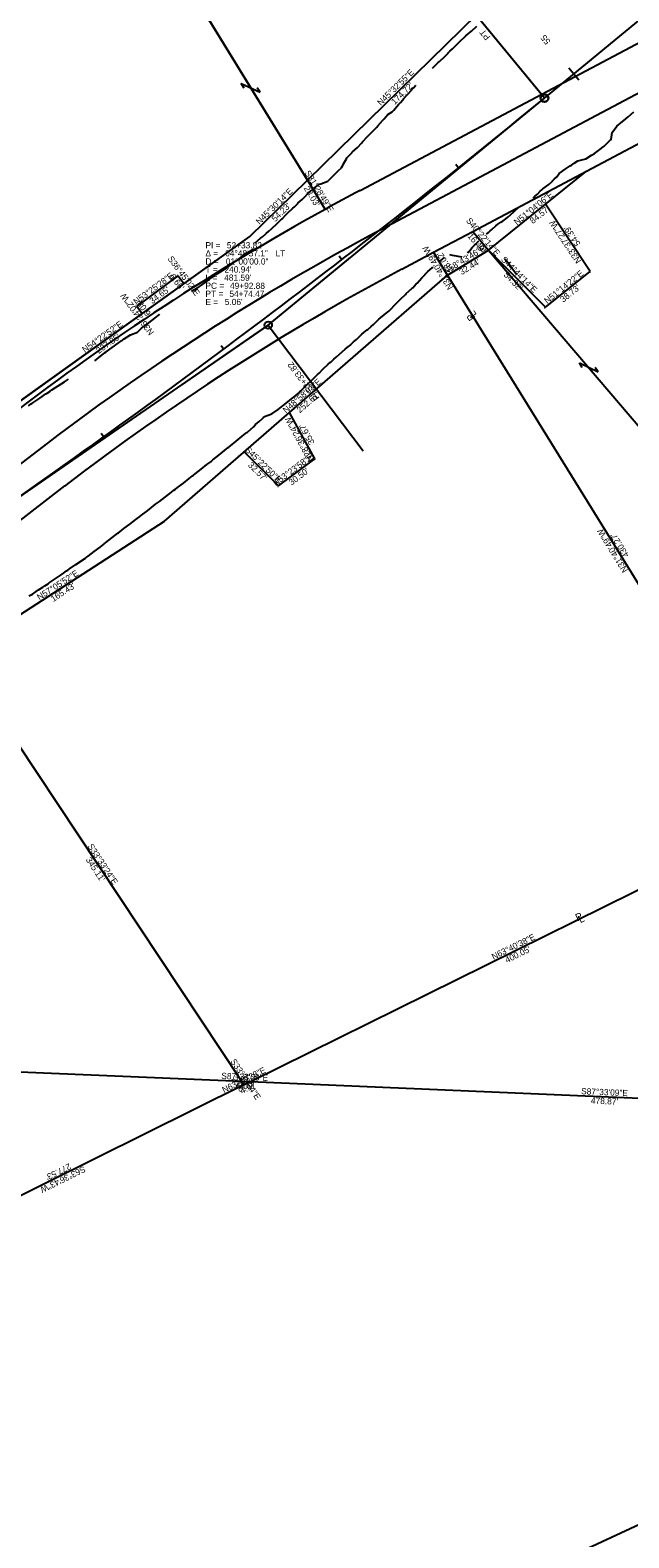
# Model space of a CAD drawing. Extents: x 1145508 to 2262867, y -3126236 to 2021677.
# Drawn here: x 1148331 to 1148734, y 2017346 to 2018362 of the extents above; entities that cross this region are included whole.
import ezdxf

# ---------------------------------------------------------------- set-up
doc = ezdxf.new("R2010")
doc.units = 0
for name, color, linetype in [('Default', 7, 'Continuous'), ('DSN_RDWY_Alignment', 7, 'Continuous'), ('DSN_RDWY_Alignment Annotation', 7, 'Continuous'), ('DSN_RDWY_Const Limits', 7, 'Continuous'), ('DSN_ROW_Annotation', 7, 'Continuous'), ('DSN_ROW_Esmnt', 7, 'Continuous'), ('DSN_ROW_Line', 7, 'Continuous'), ('DSN_ROW_Prop-Line', 7, 'Continuous'), ('DSN_ROW_Prop-Line-Annotation', 7, 'Continuous'), ('E_Const Align', 7, 'Continuous'), ('EX_QSECTION', 7, 'Continuous'), ('EX_ROW', 7, 'Continuous'), ('EX_ROW_ANNOT', 7, 'Continuous'), ('EX_SIGN', 7, 'Continuous'), ('EX_WATER_UTILITIES_ANNOT', 7, 'Continuous')]:
    doc.layers.add(name, color=color, linetype=linetype)

msp = doc.modelspace()

# ---------------------------------------------------------------- linework, layer by layer
at = {"layer": 'Default'}
for p, q in [((1148805.7, 2018354.2), (1148567.3, 2018227.7)), ((1148336, 2018078.8), (1147725.2, 2017608.5))]:
    msp.add_line(p, q, dxfattribs=at)
msp.add_arc((1149334.7, 2016781.7), 1637, 117.9535, 127.5937, dxfattribs=at)
at = {"layer": 'DSN_RDWY_Alignment'}
for p, q in [((1148491.5, 2018163.5), (1148677.5, 2018316.5)), ((1148293.2, 2018026.5), (1148491.5, 2018163.5))]:
    msp.add_line(p, q, dxfattribs=at)
for points in [[(1148677.5, 2018316.5), (1148603.6, 2018406.4)], [(1148491.5, 2018163.5), (1148555.3, 2018078.8)]]:
    msp.add_lwpolyline(points, dxfattribs=at)
for centre in [(1148677.5, 2018316.5), (1148491.5, 2018163.5)]:
    msp.add_circle(centre, 2.5, dxfattribs=at)
at = {"layer": 'DSN_RDWY_Alignment Annotation'}
for p, q in [((1148675.8, 2018318.6), (1148620.3, 2018386)), ((1148693.9, 2018336.9), (1148700.6, 2018328.7)), ((1148677.5, 2018316.5), (1148677.5, 2018316.5)), ((1148617.8, 2018271.9), (1148619.7, 2018269.6)), ((1148491.5, 2018163.5), (1148547.1, 2018209.2)), ((1148539.3, 2018210.1), (1148541.1, 2018207.8)), ((1148491.5, 2018163.5), (1148432.2, 2018122.5)), ((1148491.5, 2018163.5), (1148527.6, 2018115.6)), ((1148459.7, 2018149.7), (1148461.5, 2018147.3)), ((1148527.6, 2018115.6), (1148527.6, 2018115.6)), ((1148379, 2018090.7), (1148380.8, 2018088.2))]:
    msp.add_line(p, q, dxfattribs=at)
msp.add_circle((1148677.5, 2018316.5), 2.67, dxfattribs=at)
at = {"layer": 'DSN_RDWY_Const Limits'}
for points in [[(1148602.1, 2018336.7), (1148603.2, 2018337.7), (1148605.1, 2018339.6), (1148606, 2018340.4), (1148606.8, 2018341.1), (1148610.4, 2018344.5), (1148612.6, 2018346.8), (1148612.7, 2018347), (1148612.9, 2018347.2), (1148613.8, 2018348.1), (1148615.5, 2018349.8), (1148617.4, 2018351.6), (1148620.9, 2018355), (1148623.8, 2018357.7), (1148624.5, 2018358.4), (1148626.1, 2018359.8), (1148628.3, 2018361.7), (1148632, 2018365)], [(1148482.4, 2018218.8), (1148486.3, 2018222), (1148487.6, 2018223.1), (1148489.9, 2018225), (1148490.1, 2018225.2), (1148491.9, 2018226.8), (1148493.8, 2018228.5), (1148497.4, 2018231.9), (1148498.5, 2018233.1), (1148500.7, 2018235.2), (1148501, 2018235.4), (1148503.1, 2018237.5), (1148504.5, 2018238.9), (1148508.1, 2018242.3), (1148509.1, 2018243.3), (1148511.5, 2018245.5), (1148511.7, 2018245.8), (1148514.3, 2018248.2), (1148515.4, 2018249.2), (1148518.9, 2018252.8), (1148519.6, 2018253.6), (1148522.2, 2018255.8), (1148522.6, 2018256.1), (1148525.9, 2018258.4), (1148526.8, 2018258.8), (1148531.7, 2018260.5), (1148532.2, 2018261.1), (1148534.7, 2018263.6), (1148535.2, 2018264.1), (1148538.5, 2018267.4), (1148538.7, 2018267.6), (1148540.7, 2018269.6), (1148540.8, 2018269.7), (1148541.9, 2018271.6), (1148542.2, 2018272.1), (1148544.1, 2018275.5), (1148544.5, 2018276.3), (1148548, 2018279.9), (1148548.1, 2018280), (1148551.6, 2018283.3), (1148551.8, 2018283.5), (1148554.3, 2018286.2), (1148555, 2018287), (1148558.4, 2018290.7), (1148558.9, 2018291.2), (1148561.9, 2018294.2), (1148561.9, 2018294.3), (1148564.5, 2018297), (1148565.3, 2018297.9), (1148568.7, 2018301.6), (1148569.5, 2018302.6), (1148571.8, 2018305.2), (1148572, 2018305.4), (1148574.9, 2018307.3), (1148576, 2018308.4), (1148577, 2018309.4), (1148579.3, 2018312.1), (1148580.5, 2018313.5), (1148582.1, 2018315.4), (1148582.6, 2018315.9), (1148584.8, 2018318.4), (1148585.9, 2018319.7), (1148589.2, 2018323.5), (1148590.8, 2018325.2)], [(1148669.8, 2018249.1), (1148671.1, 2018250.3), (1148671.7, 2018250.8), (1148672.7, 2018251.8), (1148674.7, 2018253.7), (1148675.7, 2018254.6), (1148676.4, 2018255.3), (1148680.5, 2018258.2), (1148682.8, 2018260.5), (1148682.9, 2018260.7), (1148683.1, 2018260.9), (1148684, 2018261.9), (1148685.9, 2018263.4), (1148687.5, 2018265.6), (1148691.5, 2018268.6), (1148694.8, 2018270.8), (1148695.7, 2018271.4), (1148697.5, 2018272.6), (1148699.9, 2018274.3), (1148705.4, 2018275.5), (1148709.2, 2018278), (1148709.6, 2018278.3), (1148711.1, 2018279.2), (1148713.8, 2018281.1), (1148717.8, 2018284.1), (1148721.4, 2018287.6), (1148722.4, 2018288.7), (1148723.2, 2018293.3), (1148726.3, 2018297.5), (1148730.1, 2018300.7), (1148730.9, 2018301.4), (1148733.9, 2018303.9), (1148737.7, 2018307.2)], [(1148638.5, 2018224.8), (1148639.8, 2018225.9), (1148641, 2018227), (1148642, 2018227.9), (1148644.7, 2018230.3), (1148646.1, 2018231.5), (1148648.2, 2018232.9), (1148648.9, 2018233.2), (1148651.5, 2018235.2), (1148652.8, 2018236.3), (1148656.6, 2018239.7), (1148658.3, 2018241.3), (1148659.5, 2018242.4)], [(1148439.8, 2018186.3), (1148441.3, 2018187.2), (1148442.7, 2018188), (1148443.3, 2018188.3), (1148443.6, 2018188.5), (1148447.4, 2018191.1), (1148451.4, 2018194.1), (1148453.3, 2018195.5), (1148455, 2018196.8), (1148455.3, 2018197), (1148456.1, 2018197.5), (1148459.5, 2018199.7), (1148463.8, 2018202.4), (1148465.7, 2018203.7), (1148467.4, 2018205), (1148467.8, 2018205.3), (1148468.9, 2018206.1), (1148471.8, 2018208.2), (1148475.8, 2018211.2), (1148477.5, 2018212.3), (1148477.5, 2018212.3), (1148479.7, 2018213.6), (1148480, 2018213.8), (1148481.7, 2018214.8)], [(1148625.8, 2018212), (1148626.4, 2018212.8), (1148626.5, 2018212.8), (1148628.9, 2018215.8), (1148629.8, 2018216.7), (1148633.3, 2018220.4)], [(1148330.5, 2017980.8), (1148331.4, 2017981.4), (1148332.6, 2017982.2), (1148336.8, 2017985), (1148339.7, 2017986.9), (1148341, 2017987.8), (1148343.2, 2017989.2), (1148344, 2017989.8), (1148345.2, 2017990.6), (1148349.4, 2017993.4), (1148352.7, 2017995.7), (1148353.6, 2017996.3), (1148355.7, 2017997.8), (1148356.5, 2017998.3), (1148357.7, 2017999.2), (1148361.8, 2018002.1), (1148365.6, 2018004.6), (1148366, 2018004.9), (1148368.3, 2018006.5), (1148368.9, 2018006.9), (1148370.1, 2018007.8), (1148374.2, 2018010.8), (1148378.2, 2018013.9), (1148378.2, 2018013.9), (1148380.5, 2018015.7), (1148381, 2018016.1), (1148382.2, 2018017), (1148386.2, 2018020.1), (1148390.2, 2018023.2), (1148390.7, 2018023.5), (1148392.6, 2018025), (1148392.9, 2018025.3), (1148394.2, 2018026.3), (1148398.2, 2018029.4), (1148402.2, 2018032.5), (1148403.1, 2018033.1), (1148404.7, 2018034.3), (1148405, 2018034.5), (1148406.2, 2018035.5), (1148410.3, 2018038.6), (1148414.3, 2018041.7), (1148415.6, 2018042.7), (1148416.9, 2018043.7), (1148416.9, 2018043.7), (1148418.3, 2018044.7), (1148422.3, 2018047.8), (1148426.3, 2018050.8), (1148428, 2018052.2), (1148428.9, 2018052.9), (1148429, 2018053), (1148430.3, 2018054), (1148434.3, 2018057), (1148438.3, 2018060.1), (1148440.5, 2018061.8), (1148440.9, 2018062.2), (1148441.1, 2018062.3), (1148442.3, 2018063.2), (1148446.3, 2018066.3), (1148450.2, 2018069.5), (1148452.7, 2018071.4), (1148452.8, 2018071.5), (1148453.2, 2018071.9), (1148454.2, 2018072.6), (1148458.1, 2018075.8), (1148462, 2018079), (1148464.5, 2018080.9), (1148465, 2018081.3), (1148465.1, 2018081.4), (1148466, 2018082.1), (1148469.9, 2018085.3), (1148473.8, 2018088.6), (1148476.1, 2018090.4), (1148477, 2018091), (1148477.2, 2018091.2), (1148477.8, 2018091.6), (1148481.6, 2018095), (1148483, 2018096.4), (1148485.3, 2018098.5), (1148487.3, 2018100.4), (1148488.4, 2018101.5), (1148488.8, 2018101.9), (1148488.9, 2018102), (1148494, 2018103.7), (1148498.1, 2018106.6), (1148500.3, 2018108.3), (1148501.6, 2018109.3), (1148502.1, 2018109.7), (1148502.4, 2018109.9), (1148506.1, 2018112.8), (1148510, 2018116), (1148511.8, 2018117.7), (1148513.3, 2018119.1), (1148513.7, 2018119.5), (1148514.4, 2018120.1), (1148517.3, 2018123), (1148521, 2018126.5), (1148522.7, 2018128.2), (1148524.3, 2018129.8), (1148524.6, 2018130.1), (1148525.7, 2018131.1), (1148528.3, 2018133.7), (1148531.9, 2018137.2), (1148533.5, 2018138.6), (1148533.6, 2018138.6), (1148535.4, 2018140.3), (1148535.7, 2018140.5), (1148537.2, 2018141.9), (1148539.5, 2018143.9), (1148543.2, 2018147.3), (1148544.6, 2018148.4), (1148547, 2018150.3), (1148547.2, 2018150.5), (1148549, 2018152.2), (1148550.9, 2018153.9), (1148554.6, 2018157.3), (1148555.8, 2018158.4), (1148558.2, 2018160.4), (1148558.5, 2018160.6), (1148560.8, 2018162.6), (1148562.3, 2018163.9), (1148565.9, 2018167.4), (1148567, 2018168.3), (1148569.5, 2018170.4), (1148569.8, 2018170.6), (1148572.6, 2018173), (1148573.6, 2018173.9), (1148577.2, 2018177.6), (1148578, 2018178.4), (1148580.4, 2018180.8), (1148580.8, 2018181.2), (1148583.8, 2018184.1), (1148584.4, 2018184.7), (1148588.2, 2018188.1), (1148588.8, 2018188.7), (1148591.2, 2018191.3), (1148591.7, 2018191.8), (1148594.9, 2018195.3), (1148595.1, 2018195.6), (1148597.1, 2018197.7), (1148597.2, 2018197.8), (1148598.6, 2018199.2), (1148599, 2018199.6), (1148601.8, 2018202.1), (1148602.4, 2018202.7)], [(1148606.4, 2018206), (1148610.2, 2018209)], [(1148613.6, 2018211.1), (1148615.3, 2018210.7), (1148621.8, 2018209.6)], [(1148374.6, 2018139.5), (1148378.4, 2018142.6), (1148380.5, 2018144.2), (1148381, 2018144.6), (1148381.1, 2018144.7), (1148382.4, 2018145.5), (1148386.4, 2018148.4), (1148390.4, 2018151.4), (1148392.9, 2018153.1), (1148393, 2018153.2), (1148393.5, 2018153.5), (1148394.5, 2018154.2), (1148398.7, 2018156.9), (1148403.4, 2018158.8), (1148405.7, 2018160.9), (1148406.1, 2018161.4), (1148406.2, 2018161.4), (1148407.1, 2018162.2), (1148411.1, 2018165.1), (1148415, 2018168.1), (1148417.3, 2018170), (1148418.2, 2018170.6), (1148418.4, 2018170.8)], [(1148329.9, 2018109), (1148331.9, 2018110.4), (1148332.2, 2018110.6), (1148333.5, 2018111.6), (1148337.6, 2018114.3), (1148341.7, 2018117.1), (1148342.6, 2018117.7), (1148344.3, 2018118.8), (1148344.5, 2018119), (1148345.8, 2018119.9), (1148350, 2018122.6), (1148354.2, 2018125.3), (1148355.5, 2018126.2), (1148356.9, 2018127.1)]]:
    msp.add_lwpolyline(points, dxfattribs=at)
at = {"layer": 'DSN_ROW_Esmnt'}
for p, q in [((1148708.3, 2018199.7), (1148678.2, 2018245)), ((1148639.9, 2018214.1), (1148678.1, 2018175.5)), ((1148403, 2018176.1), (1148430.8, 2018196.8)), ((1148430.8, 2018196.8), (1148434.8, 2018191.4)), ((1148678.1, 2018175.5), (1148708.3, 2018199.7)), ((1148406.6, 2018171.2), (1148403, 2018176.1)), ((1148522.9, 2018073.4), (1148505.8, 2018104.7)), ((1148475.3, 2018078.1), (1148498.4, 2018055.2)), ((1148498.4, 2018055.2), (1148522.9, 2018073.4))]:
    msp.add_line(p, q, dxfattribs=at)
at = {"layer": 'DSN_ROW_Line'}
for p, q in [((1148517.8, 2018261.2), (1148642.5, 2018383.5)), ((1148639.9, 2018214.1), (1148705.7, 2018267.2)), ((1148479.1, 2018223.2), (1148517.8, 2018261.2)), ((1148285.7, 2018084.7), (1148479.1, 2018223.2)), ((1148612.2, 2018197.2), (1148639.9, 2018214.1)), ((1148421.6, 2018031.4), (1148612.2, 2018197.2)), ((1148282.7, 2017941.5), (1148421.6, 2018031.4))]:
    msp.add_line(p, q, dxfattribs=at)
at = {"layer": 'DSN_ROW_Prop-Line'}
for p, q in [((1148375.9, 2018492.8), (1148517.8, 2018261.2)), ((1148517.8, 2018261.2), (1148529.8, 2018241.5)), ((1148629.2, 2018226.6), (1148639.9, 2018214.1)), ((1148612.2, 2018197.2), (1148602.7, 2018212.6)), ((1148639.9, 2018214.1), (1148927.8, 2017875.4)), ((1148838.2, 2017831.1), (1148612.2, 2018197.2)), ((1148282.7, 2017941.5), (1148473.5, 2017653.9)), ((1148479.6, 2017653.7), (1148838.2, 2017831.1)), ((1148473.5, 2017653.9), (1148475.1, 2017651.5)), ((1148475.1, 2017651.5), (1148479.6, 2017653.7)), ((1148475.1, 2017651.5), (1148226.5, 2017528.1))]:
    msp.add_line(p, q, dxfattribs=at)
at = {"layer": 'DSN_ROW_Prop-Line-Annotation'}
for p, q in [((1148475.3, 2018323.3), (1148473.3, 2018326.3)), ((1148473.3, 2018326.3), (1148486, 2018320.4)), ((1148486, 2018320.4), (1148484.1, 2018323.4)), ((1148702.9, 2018135), (1148701, 2018138)), ((1148701, 2018138), (1148713.6, 2018132.1)), ((1148713.6, 2018132.1), (1148711.7, 2018135))]:
    msp.add_line(p, q, dxfattribs=at)
at = {"layer": 'E_Const Align'}
msp.add_line((1148677.5, 2018316.5), (1149639.9, 2019108.3), dxfattribs=at)
msp.add_arc((1145037.3, 2022741.1), 5729.6, 304.6295, 309.4453, dxfattribs=at)
msp.add_arc((1145037.3, 2022741.1), 5729.6, 304.6295, 309.4453, dxfattribs=at)
at = {"layer": 'EX_QSECTION'}
for p, q in [((1148150.8, 2017667.7), (1148473.5, 2017653.9)), ((1148473.5, 2017653.9), (1148479.6, 2017653.7)), ((1148479.6, 2017653.7), (1148958, 2017633.2))]:
    msp.add_line(p, q, dxfattribs=at)
at = {"layer": 'EX_ROW'}
for p, q in [((1148553.3, 2018254.2), (1148791.6, 2018380.7)), ((1148705.7, 2018267.2), (1148761.6, 2018296.9)), ((1148629.2, 2018226.6), (1148705.7, 2018267.2)), ((1148602.7, 2018212.6), (1148629.2, 2018226.6)), ((1148581.4, 2018201.2), (1148602.7, 2018212.6)), ((1148354.3, 2018055.1), (1148257.1, 2017980.2)), ((1147579.4, 2016815.9), (1148951.2, 2017452.8))]:
    msp.add_line(p, q, dxfattribs=at)
for radius, start, end in [(1667, 117.9535, 118.871), (1667, 118.871, 127.5937), (1607, 117.9535, 127.5937)]:
    msp.add_arc((1149334.7, 2016781.7), radius, start, end, dxfattribs=at)
at = {"layer": 'EX_SIGN'}
msp.add_line((1148651, 2018208.1), (1148658.7, 2018197.9), dxfattribs=at)
at = {"layer": 'EX_WATER_UTILITIES_ANNOT'}
msp.add_lwpolyline([(1148078.7, 2018287.7), (1148226.7, 2018061.5), (1148261.5, 2018084.9), (1148285.7, 2018084.7), (1148479.1, 2018223.2), (1148517.8, 2018261.2), (1148375.9, 2018492.8)], close=True, dxfattribs=at)

# ---------------------------------------------------------------- texts
at = {"layer": 'DSN_RDWY_Alignment Annotation'}
for s, rotation, p in [('PT', 129.4453, (1148641.3, 2018357.7)), ('55', 129.4453, (1148681.8, 2018354.8)), ('52+33.82', 127.0374, (1148521.7, 2018120.4)), ('PI ', 127.0374, (1148526.2, 2018114.5))]:
    msp.add_text(s, height=4.2, rotation=rotation, dxfattribs=at).set_placement(p)
for s, p in [('Δ = ', (1148449.2, 2018209.8)), ('PI = ', (1148449.2, 2018215.2)), ('04°48\'57.1"', (1148462.5, 2018209.8)), ('52+33.82', (1148463.6, 2018215.2)), (' LT', (1148494.8, 2018209.8)), ('T = ', (1148449.2, 2018198.9)), ('D = ', (1148449.2, 2018204.3)), ("240.94'", (1148462, 2018198.9)), ('01°00\'00.0"', (1148462.9, 2018204.3)), ('L = ', (1148449.2, 2018193.4)), ('PC = ', (1148449.2, 2018187.9)), ("481.59'", (1148461.8, 2018193.4)), ('49+92.88', (1148465.7, 2018187.9)), ('PT = ', (1148449.2, 2018182.5)), ('54+74.47', (1148465.3, 2018182.5)), ('E = ', (1148449.2, 2018177)), ("5.06'", (1148462.2, 2018177))]:
    msp.add_text(s, height=4.2, dxfattribs=at).set_placement(p)
at = {"layer": 'DSN_ROW_Annotation'}
for s, rotation, p in [('N45°32\'55"E', 44.4515, (1148567.3, 2018311.1)), ("174.72'", 44.4515, (1148576.7, 2018311.8)), ('S31°28\'49"E', 301.4802, (1148515.8, 2018266.1)), ('N45°30\'14"E', 44.4962, (1148485.6, 2018230.9)), ("23.03'", 301.4802, (1148515.2, 2018255.7)), ('N51°04\'06"E', 38.9316, (1148659, 2018230.6)), ("54.23'", 44.4962, (1148496.2, 2018232.8)), ("84.57'", 38.9316, (1148669.7, 2018231.5)), ('S40°22\'14"E', 310.3706, (1148624.4, 2018233.7)), ('N33°37\'27"W', 123.6242, (1148702.5, 2018206.8)), ("16.49'", 310.3706, (1148625.4, 2018223.3)), ("54.39'", 123.6242, (1148702, 2018218.4)), ('N31°40\'49"W', 121.6803, (1148616.2, 2018189)), ("18.02'", 121.6803, (1148616.1, 2018200.6)), ('N58°43\'46"E', 31.2707, (1148611, 2018197.6)), ('S36°45\'02"E', 306.7506, (1148423.5, 2018208.1)), ("32.44'", 31.2707, (1148621.7, 2018197.1)), ('S44°44\'14"E', 314.7372, (1148647.9, 2018207.3)), ('N53°25\'28"E', 36.5756, (1148402.6, 2018177)), ("6.66'", 306.7506, (1148424.8, 2018196.2)), ("54.32'", 314.7372, (1148649.7, 2018197)), ('N51°14\'22"E', 38.7606, (1148679.4, 2018177.6)), ('N36°24\'02"W', 126.4006, (1148414.8, 2018158.6)), ("34.65'", 36.5756, (1148413.4, 2018177.5)), ("38.73'", 38.7606, (1148690.1, 2018178.5)), ("6.08'", 126.4006, (1148412.7, 2018171.5)), ('N54°22\'52"E', 35.619, (1148368, 2018144.7)), ("237.85'", 35.619, (1148377.4, 2018144)), ('N48°58\'03"E', 41.0325, (1148503.5, 2018103.8)), ("252.61'", 41.0325, (1148512.8, 2018104)), ('N28°36\'24"W', 118.6066, (1148522.2, 2018072.7)), ("35.67'", 118.6066, (1148522.8, 2018084.3)), ('S45°22\'50"E', 315.3805, (1148475.5, 2018079)), ("32.57'", 315.3805, (1148477.5, 2018068.7)), ('N53°23\'58"E', 36.6006, (1148496.5, 2018054.8)), ("30.50'", 36.6006, (1148507.2, 2018055.3)), ('N31°40\'49"W', 121.6803, (1148733.9, 2017998.3)), ("430.27'", 121.6803, (1148734.7, 2018008.4)), ('N57°05\'52"E', 32.9022, (1148337.4, 2017977.9)), ("165.43'", 32.9022, (1148346.7, 2017976.8)), ('S33°33\'24"E', 303.5568, (1148369.6, 2017812.2)), ("345.11'", 303.5568, (1148368.4, 2017803.1)), ('N63°40\'38"E', 26.3227, (1148643.2, 2017735.6)), ("400.05'", 26.3227, (1148652.3, 2017733.4)), ('N63°40\'38"E', 26.3227, (1148461.7, 2017645.8)), ('S33°33\'24"E', 303.5568, (1148465.8, 2017667.2)), ("2.96'", 303.5568, (1148466.5, 2017655.3)), ("4.97'", 26.3227, (1148473.8, 2017645.1)), ('S63°36\'43"W', 206.3879, (1148367.1, 2017596.9)), ("277.53'", 206.3879, (1148357.4, 2017598.7))]:
    msp.add_text(s, height=4.2, rotation=rotation, dxfattribs=at).set_placement(p)
at = {"layer": 'DSN_ROW_Esmnt'}
for p in [(1148429.8, 2018195.8), (1148707.3, 2018198.7), (1148402, 2018175.1), (1148677.1, 2018174.5), (1148521.9, 2018072.4), (1148497.4, 2018054.2)]:
    msp.add_text('b', height=2, dxfattribs=at).set_placement(p)
at = {"layer": 'DSN_ROW_Prop-Line-Annotation'}
for s, rotation, p in [('L', 125.8934, (1148632.1, 2018170.7)), ('P', 125.8934, (1148631.3, 2018168.6)), ('P', 26.0486, (1148699.8, 2017761.5)), ('L', 26.0486, (1148701.7, 2017760.3))]:
    msp.add_text(s, height=5, rotation=rotation, dxfattribs=at).set_placement(p)
at = {"layer": 'EX_ROW_ANNOT'}
for s, p in [('S87°33\'09"E', (1148459.8, 2017655.4)), ('S87°33\'09"E', (1148459.8, 2017655.4)), ("6.09'", (1148469.9, 2017649)), ("6.09'", (1148469.9, 2017649)), ('S87°33\'09"E', (1148702.1, 2017645.1)), ('S87°33\'09"E', (1148702.1, 2017645.1)), ("478.87'", (1148708.7, 2017638.8)), ("478.87'", (1148708.7, 2017638.8))]:
    msp.add_text(s, height=4.2, rotation=357.5526, dxfattribs=at).set_placement(p)

doc.saveas('drawing.dxf')
